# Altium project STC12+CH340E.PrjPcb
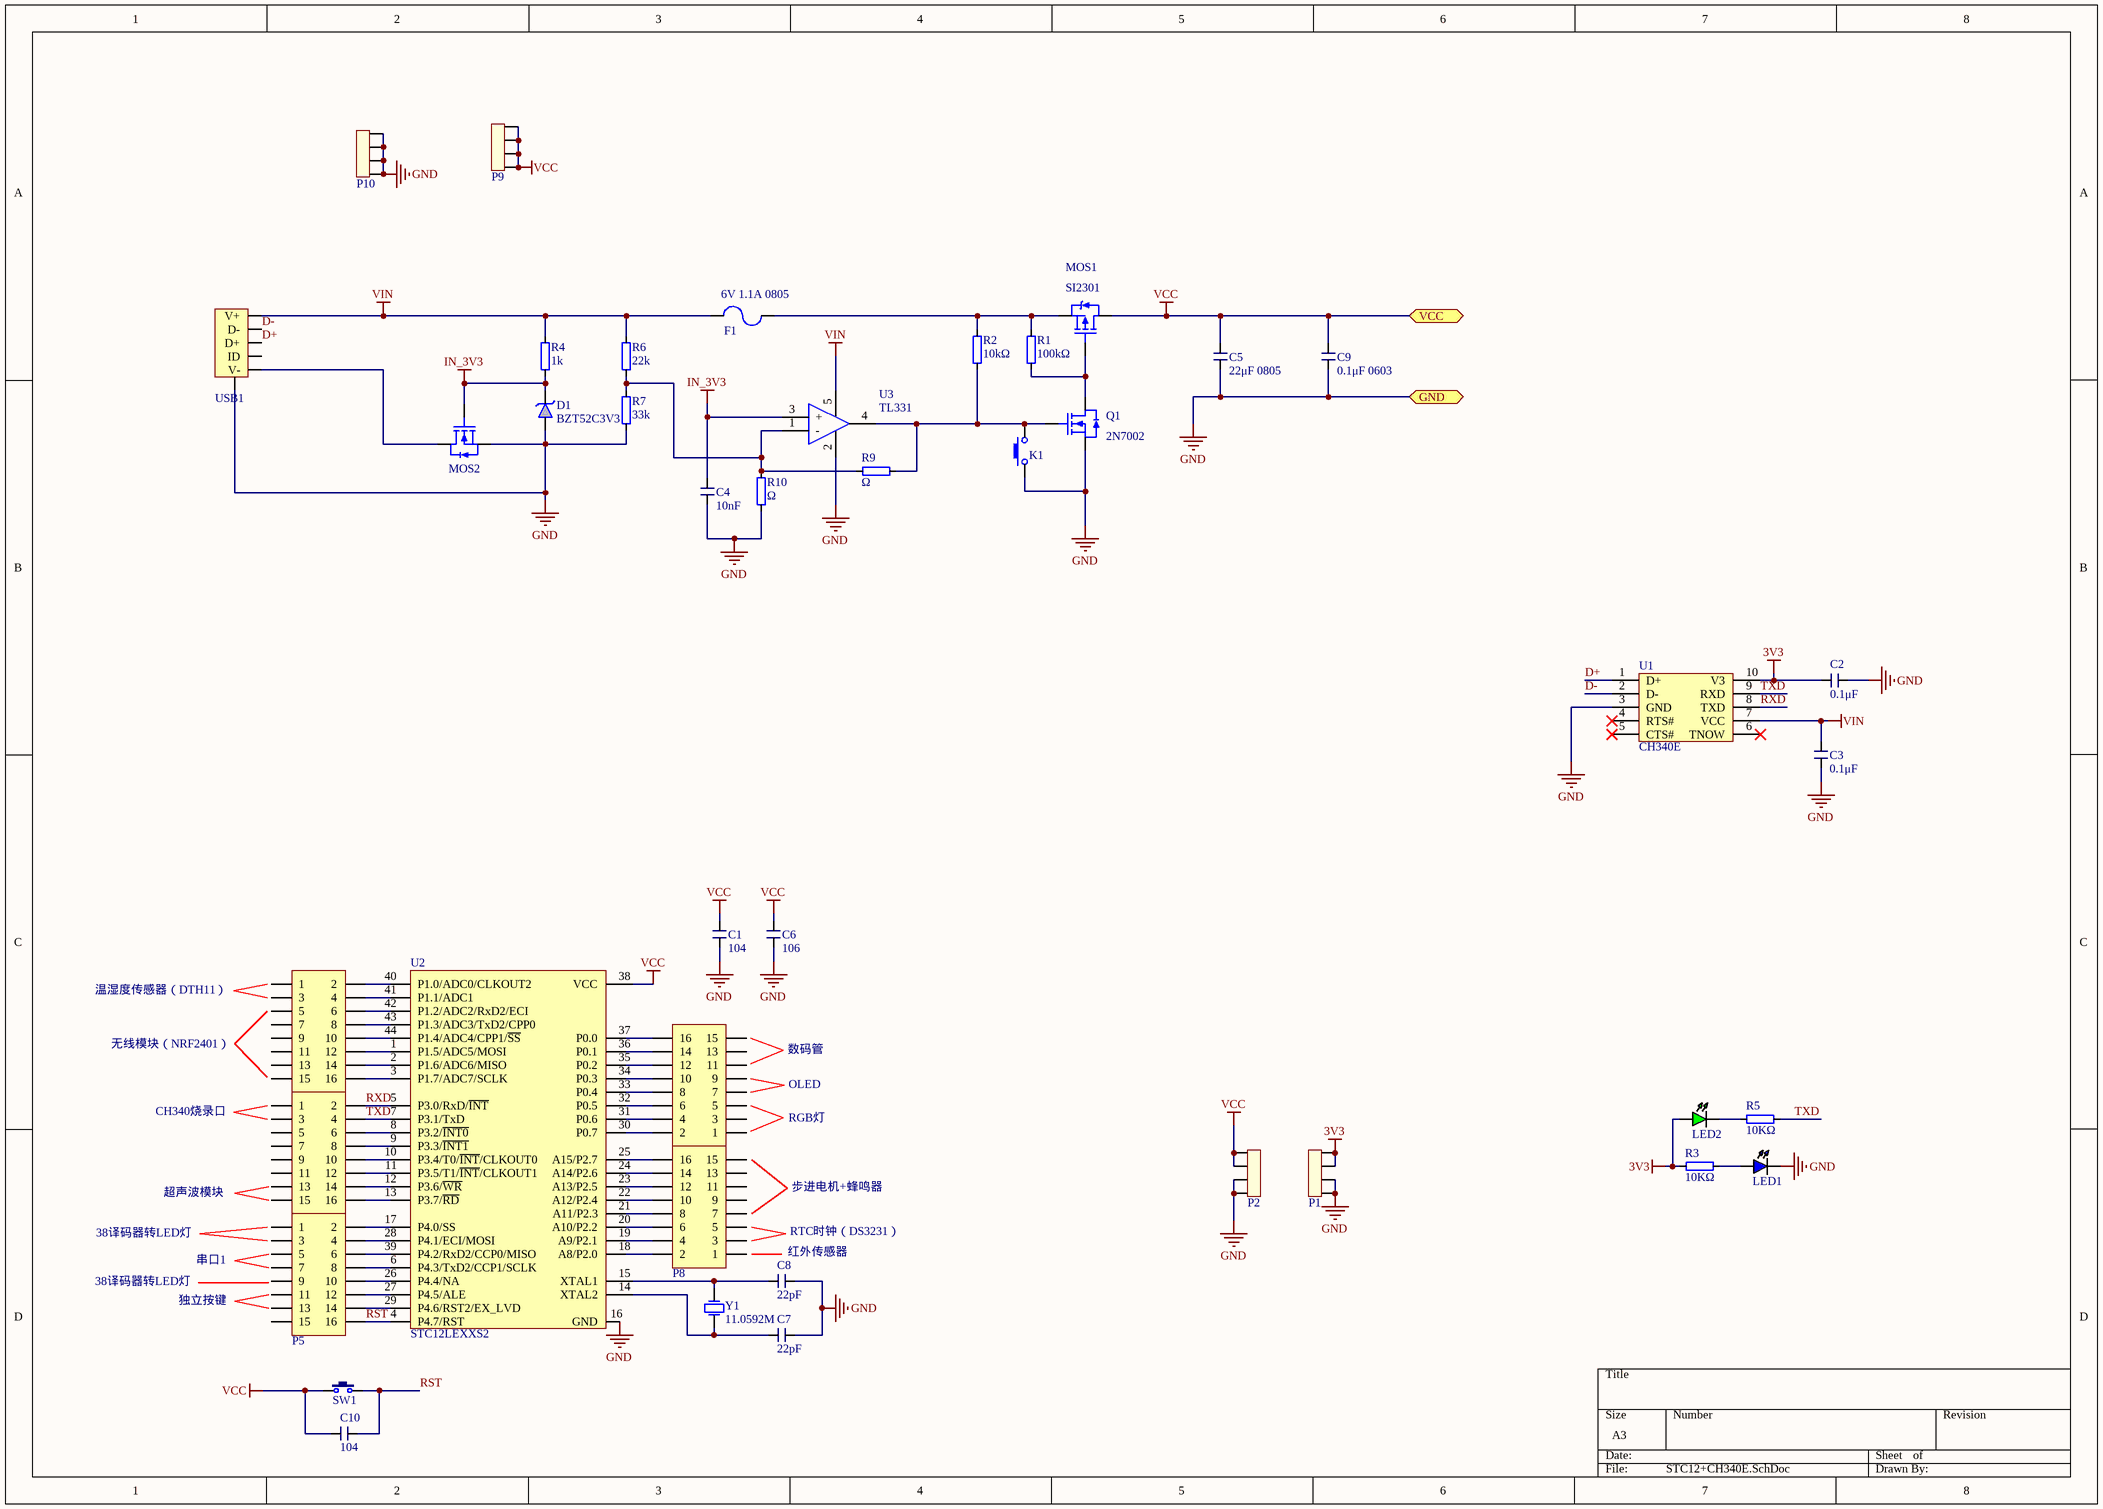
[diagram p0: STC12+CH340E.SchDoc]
1 sheet, 42 parts. Net scope: flat (ports and power ports of the same name join across sheets).

## Sheet STC12+CH340E.SchDoc
size A3

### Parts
C1  104  [C_0603]
C2  0.1μF  [C_0603]
C3  0.1μF  [C_0603]
C4  10nF  [C_0603]
C5  22μF 0805  [C_0805]
C6  106  [C_0603]
C7  22pF  [C_0603]
C8  22pF  [C_0603]
C9  0.1μF 0603  [C_0603]
C10  104  [C_0603]
D1  BZT52C3V3  [SOD_123]
F1  6V 1.1A 0805  [FB_0805]
K1  TACT SWITCH_2_SMD  [TACT SWITCH_2_SMD]  (value not drawn)
LED1  LED_0603-B  [LED_0603-B]  (value not drawn)
LED2  LED_0603-G  [LED_0603-G]  (value not drawn)
MOS1  SI2301  [SOT_23_3]
MOS2  AO3400A  [SOT_23_3]  (value not drawn)
P1  PIN4  [PIN_4]  (value not drawn)
P2  PIN4  [PIN_4]  (value not drawn)
P3  Header 8X2  [HDR-8X2]  (value not drawn)
P4  Header 8X2  [HDR-8X2]  (value not drawn)
P5  Header 8X2  [HDR-8X2]  (value not drawn)
P7  Header 8X2  [HDR-8X2]  (value not drawn)
P8  Header 8X2  [HDR-8X2]  (value not drawn)
P9  PIN4  [PIN_4]  (value not drawn)
P10  PIN4  [PIN_4]  (value not drawn)
Q1  2N7002  [SOT_23_3]
R1  100kΩ  [R_0603]
R2  10kΩ  [R_0603]
R3  10KΩ  [R_0603]
R4  1k  [R_0603]
R5  10KΩ  [R_0603]
R6  22k  [R_0603]
R7  33k  [R_0603]
R9  Ω  [R_0603]
R10  Ω  [R_0603]
SW1  3x6x5  [TSW SMD-3*6*2.5]  (value not drawn)
U1  CH340E  [MSOP_10]
U2  STC12LEXXS2  [LQFP_44]
U3  TL331  [SOT_23_5]
USB1  MICRO USB B  [MICRO USB B]  (value not drawn)
Y1  11.0592M  [Crystal_HC_49US]

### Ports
GND, VCC

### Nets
3V3: C2.2 LED2.1 P1.3 P1.4 R3.1 U1.10(V3)
GND: C1.2 C2.1 C3.1 C4.2 C5.2 C6.2 C7.2 C8.2 C9.2 D1.1(A) K1.1 LED1.2 MOS2.2(S) P1.1 P1.2 P2.1 P2.2 P10.1 P10.2 P10.3 P10.4 Q1.2(S) R7.1 R10.1 U1.3(GND) U2.16(GND) U3.2(GND) USB1.0(GND) ; port GND
IN_3V3: C4.1 D1.2(K) MOS2.1(G) R4.1 U3.3(+)
VCC: C1.1 C5.1 C6.1 C9.1 C10.1 MOS1.3(D) P2.3 P2.4 P9.1 P9.2 P9.3 P9.4 SW1.1 U2.38(VCC) ; port VCC
VIN: C3.2 F1.1 R4.2 R6.2 U1.7(VCC) U3.5(VCC) USB1.1(V+)
D+: U1.1(D+) USB1.3(D+)
D-: U1.2(D-) USB1.2(D-)
RST: C10.2 P5.16 SW1.2 U2.4(P4.7/RST)
RXD: P7.2 U1.8(TXD) U2.5(P3.0/RxD/~{INT})
TXD: P7.4 R5.2 U1.9(RXD) U2.7(P3.1/TxD)
NetC7_1: C7.1 U2.14(XTAL2) Y1.1(OSC1)
NetC8_1: C8.1 U2.15(XTAL1) Y1.2(OSC2)
NetF1_2: F1.2 MOS1.2(S) R1.2 R2.2
NetK1_2: K1.2 Q1.1(G) R2.1 R9.2 U3.4(OUT)
NetLED1_1: LED1.1 R3.2
NetLED2_2: LED2.2 R5.1
NetMOS1_1: MOS1.1(G) Q1.3(D) R1.1
NetMOS2_3: MOS2.3(D) USB1.5(V-)
NetP3_2: P3.2 U2.40(P1.0/ADC0/CLKOUT2)
NetP3_4: P3.4 U2.41(P1.1/ADC1)
NetP3_6: P3.6 U2.42(P1.2/ADC2/RxD2/ECI)
NetP3_8: P3.8 U2.43(P1.3/ADC3/TxD2/CPP0)
NetP3_10: P3.10 U2.44(P1.4/ADC4/CPP1/~{SS})
NetP3_12: P3.12 U2.1(P1.5/ADC5/MOSI)
NetP3_14: P3.14 U2.2(P1.6/ADC6/MISO)
NetP3_16: P3.16 U2.3(P1.7/ADC7/SCLK)
NetP4_2: P4.2 U2.30(P0.7)
NetP4_4: P4.4 U2.31(P0.6)
NetP4_6: P4.6 U2.32(P0.5)
NetP4_8: P4.8 U2.33(P0.4)
NetP4_10: P4.10 U2.34(P0.3)
NetP4_12: P4.12 U2.35(P0.2)
NetP4_14: P4.14 U2.36(P0.1)
NetP4_16: P4.16 U2.37(P0.0)
NetP5_2: P5.2 U2.17(P4.0/SS)
NetP5_4: P5.4 U2.28(P4.1/ECI/MOSI)
NetP5_6: P5.6 U2.39(P4.2/RxD2/CCP0/MISO)
NetP5_8: P5.8 U2.6(P4.3/TxD2/CCP1/SCLK)
NetP5_10: P5.10 U2.26(P4.4/NA)
NetP5_12: P5.12 U2.27(P4.5/ALE)
NetP5_14: P5.14 U2.29(P4.6/RST2/EX_LVD)
NetP7_6: P7.6 U2.8(P3.2/~{INT0})
NetP7_8: P7.8 U2.9(P3.3/~{INT1})
NetP7_10: P7.10 U2.10(P3.4/T0/~{INT}/CLKOUT0)
NetP7_12: P7.12 U2.11(P3.5/T1/~{INT}/CLKOUT1)
NetP7_14: P7.14 U2.12(P3.6/~{WR})
NetP7_16: P7.16 U2.13(P3.7/~{RD})
NetP8_2: P8.2 U2.18(A8/P2.0)
NetP8_4: P8.4 U2.19(A9/P2.1)
NetP8_6: P8.6 U2.20(A10/P2.2)
NetP8_8: P8.8 U2.21(A11/P2.3)
NetP8_10: P8.10 U2.22(A12/P2.4)
NetP8_12: P8.12 U2.23(A13/P2.5)
NetP8_14: P8.14 U2.24(A14/P2.6)
NetP8_16: P8.16 U2.25(A15/P2.7)
NetR6_1: R6.1 R7.2 R9.1 R10.2 U3.1(-)

Not connected (* = marked no-connect by the designer): P3 1 3 5 7 9 11 13 15; P4 1 3 5 7 9 11 13 15; P5 1 3 5 7 9 11 13 15; P7 1 3 5 7 9 11 13 15; P8 1 3 5 7 9 11 13 15; U1 4(RTS#)* 5(CTS#)* 6(TNOW)*; USB1 4(ID)

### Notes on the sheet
- 温湿度传感器（DTH11）
- 无线模块（NRF2401）
- 数码管
- CH340烧录口
- OLED
- RGB灯
- 步进电机+蜂鸣器
- 38译码器转LED灯
- 超声波模块
- 串口1
- (near C8) 红外传感器
- RTC时钟（DS3231）
- 独立按键

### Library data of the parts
C1-C4 C6-C10 = C_0603
C5 = C_0805
D1 = BZT52CxVx
F1 = FUSE_0805
P3-P5 P7 P8 = Header 8X2: 8*2P接插件; 版权归属: 源创客
R1-R7 R9 R10 = R_0603
SW1 = TSW 3x6: 3x6轻触开关; 版权归属: 源创客
U2 = STC12LE5AXXS2 - LQPF44
Y1 = Crystal_HC_49US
